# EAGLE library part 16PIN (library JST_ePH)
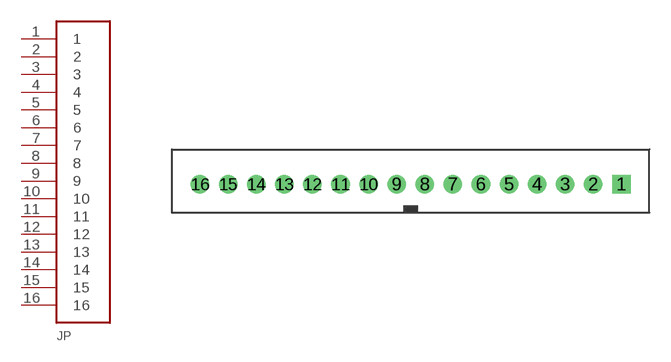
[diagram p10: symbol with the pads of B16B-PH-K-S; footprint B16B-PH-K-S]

Designator prefix JP

## 16PIN  [B16B-PH-K-S]
1  1
2  2
3  3
4  4
5  5
6  6
7  7
8  8
9  9
10  10
11  11
12  12
13  13
14  14
15  15
16  16

## Footprint B16B-PH-K-S (pad centres in mm)
drill 0.813 square: 1 15,0
drill 0.813 round: 2 13,0; 3 11,0; 4 9,0; 5 7,0; 6 5,0; 7 3,0; 8 1,0; 9 -1,0; 10 -3,0; 11 -5,0; 12 -7,0; 13 -9,0; 14 -11,0; 15 -13,0; 16 -15,0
